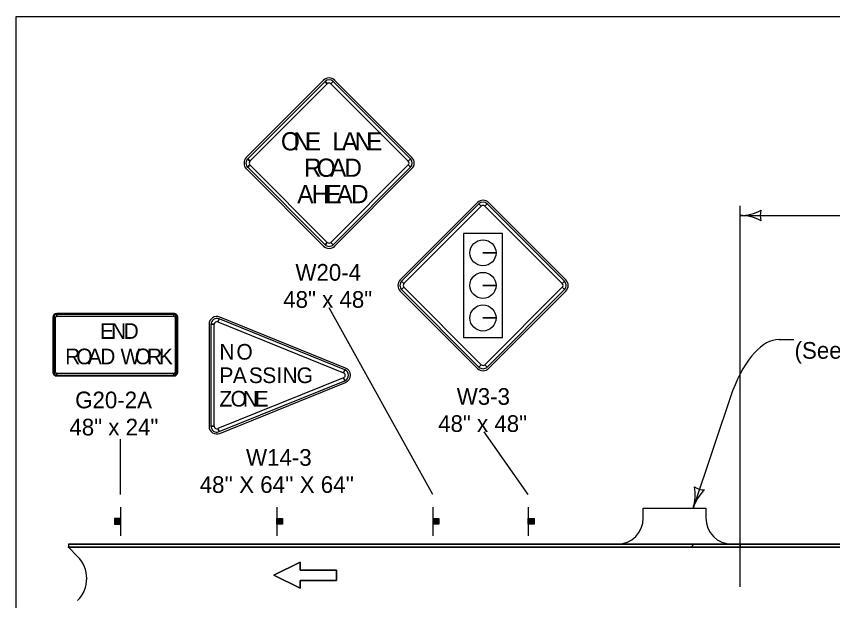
# Model space of a CAD drawing. Extents: x -2134934 to -2122394, y -2140205 to -2137036.
# Drawn here: x -2134934 to -2134151, y -2137596 to -2137036 of the extents above; entities that cross this region are included whole.
import ezdxf

# ---------------------------------------------------------------- set-up
doc = ezdxf.new("R2010")
doc.units = 0
for name, color, linetype in [('Barrier', 7, 'Continuous'), ('BridgeSuperStructureExisting', 7, 'Continuous'), ('Default', 7, 'Continuous'), ('DsnShtPlotIdentification', 7, 'Continuous'), ('DsnShtPlotShape', 7, 'Continuous')]:
    doc.layers.add(name, color=color, linetype=linetype)

msp = doc.modelspace()

# ---------------------------------------------------------------- linework, layer by layer
at = {"layer": 'Barrier'}
for p, q in [((-2134639.39, -2137097.19), (-2134713.64, -2137171.44)), ((-2134638.07, -2137098.52), (-2134635.86, -2137100.73)), ((-2134632.32, -2137100.73), (-2134630.11, -2137098.52)), ((-2134554.54, -2137171.44), (-2134628.79, -2137097.19)), ((-2134710.11, -2137174.97), (-2134712.31, -2137172.76)), ((-2134712.31, -2137180.72), (-2134710.11, -2137178.51)), ((-2134555.87, -2137172.76), (-2134558.08, -2137174.97)), ((-2134558.08, -2137178.51), (-2134555.87, -2137180.72)), ((-2134713.64, -2137182.04), (-2134639.39, -2137256.29)), ((-2134628.79, -2137256.29), (-2134554.54, -2137182.04)), ((-2134491.59, -2137214.53), (-2134565.83, -2137288.78)), ((-2134490.26, -2137215.86), (-2134488.05, -2137218.06)), ((-2134484.52, -2137218.06), (-2134482.31, -2137215.86)), ((-2134406.73, -2137288.78), (-2134480.98, -2137214.53)), ((-2134635.86, -2137252.76), (-2134638.07, -2137254.96)), ((-2134630.11, -2137254.96), (-2134632.32, -2137252.76)), ((-2134473.88, -2137262.75), (-2134486.38, -2137262.75)), ((-2134486.38, -2137262.75), (-2134473.88, -2137262.75)), ((-2134562.3, -2137292.31), (-2134564.51, -2137290.1)), ((-2134564.51, -2137298.06), (-2134562.3, -2137295.85)), ((-2134473.88, -2137294), (-2134486.38, -2137294)), ((-2134486.38, -2137294), (-2134473.88, -2137294)), ((-2134408.06, -2137290.1), (-2134410.27, -2137292.31)), ((-2134410.27, -2137295.85), (-2134408.06, -2137298.06)), ((-2134565.83, -2137299.38), (-2134491.59, -2137373.63)), ((-2134480.98, -2137373.63), (-2134406.73, -2137299.38)), ((-2134783.16, -2137320.89), (-2134895.66, -2137320.89)), ((-2134899.41, -2137324.64), (-2134899.41, -2137377.14)), ((-2134898.48, -2137324.64), (-2134896.91, -2137324.64)), ((-2134895.66, -2137323.39), (-2134895.66, -2137321.82)), ((-2134783.16, -2137321.82), (-2134783.16, -2137323.39)), ((-2134781.91, -2137324.64), (-2134780.35, -2137324.64)), ((-2134779.41, -2137377.14), (-2134779.41, -2137324.64)), ((-2134740.97, -2137329.01), (-2134739.8, -2137326.11)), ((-2134618.27, -2137373.25), (-2134739.1, -2137324.37)), ((-2134473.88, -2137325.25), (-2134486.38, -2137325.25)), ((-2134486.38, -2137325.25), (-2134473.88, -2137325.25)), ((-2134749.41, -2137331.32), (-2134749.41, -2137429.07)), ((-2134747.53, -2137331.32), (-2134744.41, -2137331.32)), ((-2134618.98, -2137374.98), (-2134620.15, -2137377.88)), ((-2134488.05, -2137370.09), (-2134490.26, -2137372.3)), ((-2134482.31, -2137372.3), (-2134484.52, -2137370.09)), ((-2134896.91, -2137377.14), (-2134898.48, -2137377.14)), ((-2134895.66, -2137379.95), (-2134895.66, -2137378.39)), ((-2134895.66, -2137380.89), (-2134783.16, -2137380.89)), ((-2134783.16, -2137378.39), (-2134783.16, -2137379.95)), ((-2134780.35, -2137377.14), (-2134781.91, -2137377.14)), ((-2134620.15, -2137382.52), (-2134618.98, -2137385.41)), ((-2134739.1, -2137436.03), (-2134618.27, -2137387.15)), ((-2134744.41, -2137429.07), (-2134747.53, -2137429.07)), ((-2134739.8, -2137434.29), (-2134740.97, -2137431.39))]:
    msp.add_line(p, q, dxfattribs=at)
for points in [[(-2134638.07, -2137098.52), (-2134712.31, -2137172.76), (-2134710.11, -2137174.97), (-2134635.86, -2137100.73), (-2134638.07, -2137098.52)], [(-2134555.87, -2137172.76), (-2134630.11, -2137098.52), (-2134632.32, -2137100.73), (-2134558.08, -2137174.97), (-2134555.87, -2137172.76)], [(-2134712.31, -2137180.72), (-2134638.07, -2137254.96), (-2134635.86, -2137252.76), (-2134710.11, -2137178.51), (-2134712.31, -2137180.72)], [(-2134630.11, -2137254.96), (-2134555.87, -2137180.72), (-2134558.08, -2137178.51), (-2134632.32, -2137252.76), (-2134630.11, -2137254.96)], [(-2134490.26, -2137215.86), (-2134564.51, -2137290.1), (-2134562.3, -2137292.31), (-2134488.05, -2137218.06), (-2134490.26, -2137215.86)], [(-2134408.06, -2137290.1), (-2134482.31, -2137215.86), (-2134484.52, -2137218.06), (-2134410.27, -2137292.31), (-2134408.06, -2137290.1)], [(-2134467.55, -2137244.13), (-2134505.02, -2137244.13), (-2134505.02, -2137344.02), (-2134467.55, -2137344.02), (-2134467.55, -2137244.13)], [(-2134564.51, -2137298.06), (-2134490.26, -2137372.3), (-2134488.05, -2137370.09), (-2134562.3, -2137295.85), (-2134564.51, -2137298.06)], [(-2134482.31, -2137372.3), (-2134408.06, -2137298.06), (-2134410.27, -2137295.85), (-2134484.52, -2137370.09), (-2134482.31, -2137372.3)], [(-2134898.48, -2137324.64), (-2134898.48, -2137377.14), (-2134896.91, -2137377.14), (-2134896.91, -2137324.64), (-2134898.48, -2137324.64)], [(-2134783.16, -2137321.82), (-2134895.66, -2137321.82), (-2134895.66, -2137323.39), (-2134783.16, -2137323.39), (-2134783.16, -2137321.82)], [(-2134780.35, -2137377.14), (-2134780.35, -2137324.64), (-2134781.91, -2137324.64), (-2134781.91, -2137377.14), (-2134780.35, -2137377.14)], [(-2134618.98, -2137374.98), (-2134739.8, -2137326.11), (-2134740.97, -2137329.01), (-2134620.15, -2137377.88), (-2134618.98, -2137374.98)], [(-2134747.53, -2137331.32), (-2134747.53, -2137429.07), (-2134744.41, -2137429.07), (-2134744.41, -2137331.32), (-2134747.53, -2137331.32)], [(-2134895.66, -2137379.95), (-2134783.16, -2137379.95), (-2134783.16, -2137378.39), (-2134895.66, -2137378.39), (-2134895.66, -2137379.95)], [(-2134739.8, -2137434.29), (-2134618.98, -2137385.41), (-2134620.15, -2137382.52), (-2134740.97, -2137431.39), (-2134739.8, -2137434.29)]]:
    msp.add_lwpolyline(points, close=True, dxfattribs=at)
for centre in [(-2134486.38, -2137262.75), (-2134486.38, -2137294), (-2134486.38, -2137325.25)]:
    msp.add_circle(centre, 12.5, dxfattribs=at)
for centre, radius, start, end in [((-2134634.09, -2137102.5), 7.5, 44.99999, 134.99974), ((-2134634.09, -2137102.5), 5.62, 44.99999, 134.99974), ((-2134634.09, -2137102.5), 2.5, 44.99999, 134.99974), ((-2134708.34, -2137176.74), 7.5, 134.99974, 224.99995), ((-2134559.85, -2137176.74), 7.5, 315.00016, 44.9998), ((-2134708.34, -2137176.74), 5.62, 134.99974, 224.99995), ((-2134708.34, -2137176.74), 2.5, 134.99974, 224.99995), ((-2134559.85, -2137176.74), 2.5, 315.00016, 44.9998), ((-2134559.85, -2137176.74), 5.62, 315.00016, 44.9998), ((-2134486.28, -2137219.83), 7.5, 44.99999, 134.99974), ((-2134486.28, -2137219.83), 5.62, 44.99999, 134.99974), ((-2134486.28, -2137219.83), 2.5, 44.99999, 134.99974), ((-2134634.09, -2137250.99), 7.5, 224.99995, 315.00016), ((-2134634.09, -2137250.99), 5.62, 224.99995, 315.00016), ((-2134634.09, -2137250.99), 2.5, 224.99995, 315.00016), ((-2134560.53, -2137294.08), 7.5, 134.99974, 224.99995), ((-2134412.04, -2137294.08), 7.5, 315.00016, 44.9998), ((-2134560.53, -2137294.08), 5.62, 134.99974, 224.99995), ((-2134560.53, -2137294.08), 2.5, 134.99974, 224.99995), ((-2134412.04, -2137294.08), 2.5, 315.00016, 44.9998), ((-2134412.04, -2137294.08), 5.62, 315.00016, 44.9998), ((-2134895.66, -2137324.64), 3.75, 90.00021, 179.99985), ((-2134783.16, -2137324.64), 3.75, 0, 90.00021), ((-2134895.66, -2137324.64), 2.81, 90.00021, 179.99985), ((-2134895.66, -2137324.64), 1.25, 90.00021, 179.99985), ((-2134783.16, -2137324.64), 2.81, 0, 90.00021), ((-2134783.16, -2137324.64), 1.25, 0, 90.00021), ((-2134741.91, -2137331.32), 7.5, 67.97571, 179.99985), ((-2134741.91, -2137331.32), 5.62, 67.97571, 179.99985), ((-2134741.91, -2137331.32), 2.5, 67.97571, 179.99985), ((-2134621.09, -2137380.2), 5.62, 292.02456, 67.97541), ((-2134621.09, -2137380.2), 7.5, 292.02456, 67.97598), ((-2134486.28, -2137368.32), 7.5, 224.99995, 315.00016), ((-2134486.28, -2137368.32), 5.62, 224.99995, 315.00016), ((-2134486.28, -2137368.32), 2.5, 224.99995, 315.00016), ((-2134895.66, -2137377.14), 3.75, 179.99985, 270.00006), ((-2134895.66, -2137377.14), 2.81, 179.99985, 270.00006), ((-2134895.66, -2137377.14), 1.25, 179.99985, 270.00006), ((-2134783.16, -2137377.14), 3.75, 270.00006, 0.00027), ((-2134783.16, -2137377.14), 2.81, 270.00006, 0.00027), ((-2134783.16, -2137377.14), 1.25, 270.00006, 0.00027), ((-2134621.09, -2137380.2), 2.5, 292.02456, 67.97541), ((-2134741.91, -2137429.07), 7.5, 179.99985, 292.02456), ((-2134741.91, -2137429.07), 5.62, 179.99985, 292.02456), ((-2134741.91, -2137429.07), 2.5, 179.99985, 292.02456)]:
    msp.add_arc(centre, radius, start, end, dxfattribs=at)
at = {"layer": 'BridgeSuperStructureExisting'}
for p, q in [((-2134239.44, -2137583.23), (-2134239.44, -2137217.69)), ((-2134239.44, -2137226.98), (-2133580.02, -2137226.98)), ((-2134534.44, -2137494.5), (-2134634.09, -2137315.49)), ((-2134202.01, -2137345.99), (-2134187.79, -2137345.99)), ((-2134246.74, -2137395.12), (-2134284.66, -2137507.67)), ((-2134443.04, -2137494.5), (-2134485.39, -2137434.54)), ((-2134834.44, -2137494.5), (-2134834.44, -2137441.62)), ((-2134834.44, -2137506.66), (-2134834.44, -2137534.16)), ((-2134684.44, -2137506.66), (-2134684.44, -2137534.16)), ((-2134534.44, -2137506.66), (-2134534.44, -2137534.16)), ((-2134443.04, -2137506.66), (-2134443.04, -2137534.16)), ((-2134839.77, -2137517.52), (-2134839.77, -2137523.11)), ((-2134839.45, -2137523.11), (-2134839.45, -2137517.52)), ((-2134839.22, -2137517.52), (-2134839.22, -2137523.11)), ((-2134838.9, -2137523.11), (-2134838.9, -2137517.52)), ((-2134838.68, -2137517.52), (-2134838.7, -2137523.11)), ((-2134838.27, -2137523.11), (-2134838.25, -2137517.52)), ((-2134838.04, -2137517.52), (-2134838.04, -2137523.11)), ((-2134837.61, -2137523.11), (-2134837.61, -2137517.52)), ((-2134837.24, -2137517.52), (-2134837.24, -2137523.11)), ((-2134836.92, -2137523.11), (-2134836.9, -2137517.52)), ((-2134836.69, -2137517.52), (-2134836.69, -2137523.11)), ((-2134836.43, -2137523.11), (-2134836.43, -2137517.52)), ((-2134836.09, -2137517.52), (-2134836.09, -2137523.11)), ((-2134835.89, -2137523.11), (-2134835.89, -2137517.52)), ((-2134835.66, -2137517.52), (-2134835.66, -2137523.11)), ((-2134835.4, -2137523.11), (-2134835.4, -2137517.52)), ((-2134835.14, -2137517.52), (-2134835.14, -2137523.11)), ((-2134834.85, -2137523.11), (-2134834.85, -2137517.52)), ((-2134684.03, -2137523.11), (-2134684.03, -2137517.52)), ((-2134683.75, -2137517.52), (-2134683.75, -2137523.11)), ((-2134683.48, -2137523.11), (-2134683.48, -2137517.52)), ((-2134683.22, -2137517.52), (-2134683.22, -2137523.11)), ((-2134683, -2137523.11), (-2134683, -2137517.52)), ((-2134682.79, -2137517.52), (-2134682.79, -2137523.11)), ((-2134682.45, -2137523.11), (-2134682.45, -2137517.52)), ((-2134682.19, -2137517.52), (-2134682.19, -2137523.11)), ((-2134681.97, -2137523.11), (-2134681.98, -2137517.52)), ((-2134681.65, -2137517.52), (-2134681.65, -2137523.11)), ((-2134681.27, -2137523.11), (-2134681.27, -2137517.52)), ((-2134680.84, -2137517.52), (-2134680.84, -2137523.11)), ((-2134680.62, -2137523.11), (-2134680.63, -2137517.52)), ((-2134680.2, -2137517.52), (-2134680.18, -2137523.11)), ((-2134679.98, -2137523.11), (-2134679.98, -2137517.52)), ((-2134679.66, -2137517.52), (-2134679.66, -2137523.11)), ((-2134679.43, -2137523.11), (-2134679.43, -2137517.52)), ((-2134679.12, -2137517.52), (-2134679.12, -2137523.11)), ((-2134534.03, -2137523.11), (-2134534.03, -2137517.52)), ((-2134533.75, -2137517.52), (-2134533.75, -2137523.11)), ((-2134533.48, -2137523.11), (-2134533.48, -2137517.52)), ((-2134533.22, -2137517.52), (-2134533.22, -2137523.11)), ((-2134533, -2137523.11), (-2134533, -2137517.52)), ((-2134532.79, -2137517.52), (-2134532.79, -2137523.11)), ((-2134532.45, -2137523.11), (-2134532.45, -2137517.52)), ((-2134532.19, -2137517.52), (-2134532.19, -2137523.11)), ((-2134531.97, -2137523.11), (-2134531.98, -2137517.52)), ((-2134531.65, -2137517.52), (-2134531.65, -2137523.11)), ((-2134531.27, -2137523.11), (-2134531.27, -2137517.52)), ((-2134530.84, -2137517.52), (-2134530.84, -2137523.11)), ((-2134530.62, -2137523.11), (-2134530.63, -2137517.52)), ((-2134530.2, -2137517.52), (-2134530.18, -2137523.11)), ((-2134529.98, -2137523.11), (-2134529.98, -2137517.52)), ((-2134529.66, -2137517.52), (-2134529.66, -2137523.11)), ((-2134529.43, -2137523.11), (-2134529.43, -2137517.52)), ((-2134529.12, -2137517.52), (-2134529.12, -2137523.11)), ((-2134442.63, -2137523.11), (-2134442.63, -2137517.52)), ((-2134442.35, -2137517.52), (-2134442.35, -2137523.11)), ((-2134442.08, -2137523.11), (-2134442.08, -2137517.52)), ((-2134441.82, -2137517.52), (-2134441.82, -2137523.11)), ((-2134441.6, -2137523.11), (-2134441.6, -2137517.52)), ((-2134441.39, -2137517.52), (-2134441.39, -2137523.11)), ((-2134441.05, -2137523.11), (-2134441.05, -2137517.52)), ((-2134440.79, -2137517.52), (-2134440.79, -2137523.11)), ((-2134440.56, -2137523.11), (-2134440.58, -2137517.52)), ((-2134440.25, -2137517.52), (-2134440.25, -2137523.11)), ((-2134439.87, -2137523.11), (-2134439.87, -2137517.52)), ((-2134439.44, -2137517.52), (-2134439.44, -2137523.11)), ((-2134439.21, -2137523.11), (-2134439.23, -2137517.52)), ((-2134438.8, -2137517.52), (-2134438.78, -2137523.11)), ((-2134438.58, -2137523.11), (-2134438.58, -2137517.52)), ((-2134438.26, -2137517.52), (-2134438.26, -2137523.11)), ((-2134438.03, -2137523.11), (-2134438.03, -2137517.52)), ((-2134437.71, -2137517.52), (-2134437.71, -2137523.11)), ((-2134875.66, -2137553.94), (-2134884.44, -2137545.16)), ((-2133574.44, -2137545.16), (-2134884.44, -2137545.16)), ((-2134884.44, -2137545.16), (-2134875.65, -2137553.95)), ((-2134247.44, -2137542.16), (-2134357.44, -2137542.16))]:
    msp.add_line(p, q, dxfattribs=at)
for points in [[(-2134332.44, -2137517.16), (-2134332.44, -2137507.67), (-2134272.44, -2137507.67), (-2134272.44, -2137517.16)], [(-2134662.04, -2137577), (-2134662.04, -2137584.5), (-2134687.04, -2137572), (-2134662.04, -2137559.5), (-2134662.04, -2137567), (-2134627.04, -2137567), (-2134627.04, -2137577), (-2134662.04, -2137577)]]:
    msp.add_lwpolyline(points, dxfattribs=at)
for points in [[(-2134834.54, -2137523.11), (-2134834.54, -2137517.48), (-2134840.16, -2137517.48), (-2134840.16, -2137523.11)], [(-2134684.35, -2137523.11), (-2134684.35, -2137517.48), (-2134678.72, -2137517.48), (-2134678.72, -2137523.11)], [(-2134534.35, -2137523.11), (-2134534.35, -2137517.48), (-2134528.72, -2137517.48), (-2134528.72, -2137523.11)], [(-2134442.95, -2137523.11), (-2134442.95, -2137517.48), (-2134437.32, -2137517.48), (-2134437.32, -2137523.11)], [(-2134627.04, -2137577), (-2134627.04, -2137567), (-2134662.04, -2137567), (-2134662.04, -2137559.5), (-2134687.04, -2137572), (-2134662.04, -2137584.5), (-2134662.04, -2137577)]]:
    msp.add_lwpolyline(points, close=True, dxfattribs=at)
for centre, radius, start, end in [((-2134357.44, -2137517.16), 25, 270, 360), ((-2134247.44, -2137517.16), 25, 180, 270), ((-2134896.87, -2137575.16), 30, 315, 45), ((-2134896.87, -2137575.16), 30, 315, 45)]:
    msp.add_arc(centre, radius, start, end, dxfattribs=at)
msp.add_ellipse((-2134202.01, -2137558.92), major_axis=(0, 212.93), ratio=0.328743, start_param=0, end_param=0.693162, dxfattribs=at)
at = {"layer": 'Default'}
msp.add_lwpolyline([(-2134934.44, -2137035.95), (-2131799.45, -2137035.95), (-2131799.45, -2139045.94), (-2134934.44, -2139045.94)], close=True, dxfattribs=at)
at = {"layer": 'DsnShtPlotIdentification'}
for p, q in [((-2134884.44, -2137542.16), (-2134884.44, -2137545.16)), ((-2134884.44, -2137542.16), (-2134884.44, -2137545.16)), ((-2134284.66, -2137542.16), (-2134884.44, -2137542.16)), ((-2134884.44, -2137545.16), (-2134285.86, -2137545.16)), ((-2134284.66, -2137542.16), (-2134285.86, -2137545.16)), ((-2134285.86, -2137545.16), (-2134284.66, -2137542.16)), ((-2134285.86, -2137545.16), (-2134239.44, -2137545.16)), ((-2134239.44, -2137542.16), (-2134284.66, -2137542.16)), ((-2133766.47, -2137542.16), (-2134239.44, -2137542.16)), ((-2134239.44, -2137542.16), (-2134239.44, -2137545.16)), ((-2134239.44, -2137545.16), (-2134239.44, -2137542.16)), ((-2134239.44, -2137545.16), (-2133764.3, -2137545.16))]:
    msp.add_line(p, q, dxfattribs=at)
for points in [[(-2134884.86, -2137545.16), (-2133574.86, -2137545.16)], [(-2134884.44, -2137542.16), (-2133574.44, -2137542.16)], [(-2134884.44, -2137545.16), (-2133574.44, -2137545.16)]]:
    msp.add_lwpolyline(points, dxfattribs=at)
at = {"layer": 'DsnShtPlotShape'}
for centre, radius, start, end in [((-2134239.44, -2137184.48), 42.5, 270, 298.07249), ((-2134203.81, -2137226.98), 16.42, 162.26665, 197.73335), ((-2134239.44, -2137269.48), 42.5, 61.92751, 90), ((-2134325.1, -2137494.6), 42.5, 342.08492, 10.15741), ((-2134244.23, -2137520.74), 42.5, 134.01243, 162.08492), ((-2134273.7, -2137473.76), 16.42, 234.35157, 269.81827)]:
    msp.add_arc(centre, radius, start, end, dxfattribs=at)

# ---------------------------------------------------------------- texts
at = {"layer": 'Barrier'}
for s, height, p in [('O', 17.5, (-2134680.38, -2137164.55)), ('N', 17.5, (-2134668.6, -2137164.55)), ('E', 17.5, (-2134657.37, -2137164.55)), ('L', 17.5, (-2134631.12, -2137164.55)), ('A', 17.5, (-2134621.93, -2137164.55)), ('N', 17.5, (-2134609.66, -2137164.55)), ('E', 17.5, (-2134598.43, -2137164.55)), ('R', 17.5, (-2134658.27, -2137189.87)), ('O', 17.5, (-2134645.98, -2137189.87)), ('A', 17.5, (-2134633.14, -2137189.87)), ('D', 17.5, (-2134619.49, -2137189.87)), ('A', 17.5, (-2134664.71, -2137215.18)), ('H', 17.5, (-2134650.84, -2137215.18)), ('E', 17.5, (-2134637.62, -2137215.18)), ('A', 17.5, (-2134626.91, -2137215.18)), ('D', 17.5, (-2134613.05, -2137215.18)), ('W20-4', 16, (-2134666.46, -2137289.49)), ('48" x 48"', 16, (-2134678.16, -2137315.49)), ('E', 15, (-2134854.09, -2137345.26)), ('N', 15, (-2134843.47, -2137345.26)), ('D', 15, (-2134831.38, -2137345.26)), ('N', 15, (-2134739.44, -2137365.2)), ('O', 15, (-2134723.1, -2137365.2)), ('R', 15, (-2134887.55, -2137369.64)), ('O', 15, (-2134876.87, -2137369.64)), ('A', 15, (-2134865.71, -2137369.64)), ('D', 15, (-2134853.85, -2137369.64)), ('W', 15, (-2134834.4, -2137369.64)), ('O', 15, (-2134820.67, -2137369.64)), ('R', 15, (-2134808.9, -2137369.64)), ('K', 15, (-2134797.6, -2137369.64)), ('P', 15, (-2134739.44, -2137387.7)), ('A', 15, (-2134726.55, -2137387.7)), ('S', 15, (-2134711.2, -2137387.7)), ('S', 15, (-2134698.31, -2137387.7)), ('I', 15, (-2134684.71, -2137387.7)), ('N', 15, (-2134678.85, -2137387.7)), ('G', 15, (-2134665.26, -2137387.7)), ('G20-2A', 16, (-2134877.94, -2137411.89)), ('Z', 15, (-2134739.44, -2137410.2)), ('O', 15, (-2134728.7, -2137410.2)), ('N', 15, (-2134716.87, -2137410.2)), ('E', 15, (-2134705.51, -2137410.2)), ('W3-3', 16, (-2134511.58, -2137408.54)), ('48" x 24"', 16, (-2134883.48, -2137437.89)), ('48" x 48"', 16, (-2134529.45, -2137434.54)), ('W14-3', 16, (-2134713.9, -2137467.03)), ("48'' X 64'' X 64''", 16, (-2134758.39, -2137493.03))]:
    msp.add_text(s, height=height, dxfattribs=at).set_placement(p)
at = {"layer": 'BridgeSuperStructureExisting'}
msp.add_text('(See Exeter Ave Advanced Signing on J.5)', height=16, dxfattribs=at).set_placement((-2134187.2, -2137364.34))

doc.saveas('drawing.dxf')
